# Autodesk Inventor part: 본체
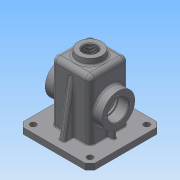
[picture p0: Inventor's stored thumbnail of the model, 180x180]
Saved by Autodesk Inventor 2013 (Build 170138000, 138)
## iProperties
Created: 2018-10
Part Number: 본체
Material: 일반
Document SubType Name: Modeling
Designer: Administrator
Density: 1 g/cm^3
Author: Administrator
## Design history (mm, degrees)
sketch "스케치1"
  geometry: L1 (-32.5, 32.5)-(32.5, 32.5); L2 (32.5, 32.5)-(32.5, -32.5); L3 (32.5, -32.5)-(-32.5, -32.5); L4 (-32.5, -32.5)-(-32.5, 32.5); L5 (-32.5, 32.5)-(32.5, -32.5); L6 (32.5, 32.5)-(-32.5, -32.5); 1 further point
  constraints: 12 end point, 2 midpoint, 2 parallel, 1 horizontal, 1 perpendicular
  dimensions: "d0" = 65 distance of L2.end L3.end; "d1" = 65 distance of L1.end L2.end
extrude "돌출1" new body sketch "스케치1" stored distance "d2" = 110; taper "d3" = 0 deg
sketch "스케치2"
  geometry: L1 (-110, 0)-(-110, 65) reference; C1 r 27.5 at (-55, 32.5); 2 further points
  constraints: 1 centre point, 1 horizontal alignment, 1 midpoint
  dimensions: "d4" = 55 diameter of C1; "d5" = 55 distance of point (-110, 32.5) C1.centre
feature "쉘1" dims "d6" = 5
fillet "모깎기1" dims "d7" = 8
fillet "모깎기2" dims "d8" = 8
extrude "돌출2" join sketch "스케치2" distance "d9" = 15; taper "d10" = 0 deg
sketch "스케치3"
  geometry: C1 r 27.5 at (0, 0) reference; C2 r 17.5 at (0, 0)
  constraints: 1 centre point, 1 coincident
  dimensions: "d11" = 35 diameter of C2
extrude "돌출3" cut sketch "스케치3" distance "d13" = 17; taper "d14" = 0 deg
sketch "스케치5"
  geometry: C1 r 27.5 at (-55, 24.5); 1 further point
  constraints: 1 centre point, 1 coincident
  dimensions: "d16" = 55 diameter of C1
extrude "돌출4" join sketch "스케치5" distance "d17" = 15; taper "d18" = 0 deg
sketch "스케치6"
  geometry: C1 r 27.5 at (0, 0) reference; C2 r 17.5 at (0, 0)
  constraints: 1 centre point, 1 coincident
  dimensions: "d20" = 35 diameter of C2
extrude "돌출5" cut sketch "스케치6" distance "d21" = 17; taper "d22" = 0 deg
sketch "스케치7"
  geometry: C1 r 17.5 at (0, 0) reference; C2 r 15 at (0, 0)
  constraints: 1 centre point, 1 coincident
  dimensions: "d23" = 30 diameter of C2
extrude "돌출6" cut sketch "스케치7" stored distance "d24" = 17; taper "d25" = 0 deg
sketch "스케치8"
  geometry: L1 (-32.5, 24.5)-(-32.5, -24.5) reference; L2 (-24.5, -32.5)-(24.5, -32.5) reference; L3 (32.5, -24.5)-(32.5, 24.5) reference; L4 (24.5, 32.5)-(-24.5, 32.5) reference; L5 (-60, 60)-(60, 60); L6 (60, 60)-(60, -60); L7 (60, -60)-(-60, -60); L8 (-60, -60)-(-60, 60); L9 (-60, 60)-(60, -60); L10 (60, 60)-(-60, -60); A1 r 8 centre (-24.5, 24.5) between (-24.5, 32.5) and (-32.5, 24.5) reference; A2 r 8 centre (-24.5, -24.5) between (-32.5, -24.5) and (-24.5, -32.5) reference; A3 r 8 centre (24.5, -24.5) between (24.5, -32.5) and (32.5, -24.5) reference; A4 r 8 centre (24.5, 24.5) between (32.5, 24.5) and (24.5, 32.5) reference; 1 further point
  constraints: 12 end point, 2 midpoint, 2 parallel, 1 horizontal, 1 perpendicular
  dimensions: "d26" = 120 distance of L5.start L5.end; "d28" = 120 distance of L5.end L6.end
extrude "돌출7" join sketch "스케치8" distance "d29" = 10; taper "d30" = 0 deg
chamfer "모따기1" distance "d31" = 8; stored, may be unused: second distance "d32" = 2, angle "d33" = 45 deg
node "작업 평면1"
sketch "스케치9"
  geometry: C1 r 20 at (0, 0); 1 further point
  constraints: 1 centre point, 1 coincident
  dimensions: "d35" = 40 diameter of C1
extrude "돌출8" join sketch "스케치9" stored distance "d36" = 10; taper "d37" = 7 deg
hole "구멍1" diameter "d40" = 22.835; stored, may be unused: countersink angle "d44" = 90 deg, drill point angle "d46" = 0 deg; dims "d41" = 20, "d42" = 4, "d43" = 2, "d45" = 20, "d116" = 10, "d117" = 10
sketch "스케치10"
  geometry: L1 (48, -45)-(40.815, -4.251); L2 (60, -45)-(60, -55) reference; L3 (52, -45)-(60, -45) reference; 1 further point
  constraints: 2 end point, 1 point on line
  dimensions: "d50" = 12 distance from line of L2 L1.start; "d52" = 10 deg angle of L2 L1
feature "리브1" sketch "스케치10" dims "d53" = 1, "d54" = 10, "d55" = 0, "d56" = 0, "d57" = 1, "d58" = 1
sketch "스케치11"
  geometry: L1 (-42.5, -29.454)-(-42.5, -45); L2 (52, -45)-(-52, -45) reference; L3 (-32.5, -45)-(-32.5, -12.49) reference; L4 (-27.5, 50)-(-27.5, -55) reference; 2 further points
  constraints: 2 end point, 1 point on line, 1 vertical
  dimensions: "d60" = 15 distance between parallel lines of L4 L1
fillet "모깎기5" dims "d61" = 3
fillet "모깎기6" dims "d62" = 3
feature "리브2" dims "d63" = 1, "d64" = 6, "d65" = 0, "d66" = 0, "d67" = 1, "d68" = 1
fillet "모깎기8" dims "d70" = 3
fillet "모깎기9" dims "d71" = 3
chamfer "모따기2" distance "d73" = 1; stored, may be unused: second distance "d74" = 2, angle "d75" = 45 deg
sketch "스케치12"
  geometry: L1 (0, 0)-(-21, 0); C1 r 18.5 at (0, 0) reference; 1 further point
  constraints: 2 end point, 1 coincident, 1 horizontal
  dimensions: "d77" = 21 distance of L1.start L1.end
hole "구멍2" sketch "스케치12" at (-21, 0) diameter "d78" = 3.242; stored, may be unused: countersink angle "d82" = 90 deg, drill point angle "d84" = 118 deg; dims "d79" = 8, "d80" = 4, "d81" = 2, "d83" = 10
fillet "모깎기11" dims "d88" = 3
chamfer "모따기3" distance "d89" = 1; stored, may be unused: second distance "d90" = 2, angle "d91" = 45 deg
fillet "모깎기15" dims "d95" = 3
fillet "모깎기17" dims "d97" = 3
sketch "스케치13"
  geometry: C1 r 5 at (-47.5, 47.5); C2 r 5 at (-47.5, -47.5); C3 r 5 at (47.5, 47.5); C4 r 5 at (47.5, -47.5); 1 further point
  constraints: 4 centre point, 2 horizontal alignment, 2 vertical alignment
  dimensions: "d99" = 10 diameter of C1; "d100" = 10 diameter of C2; "d101" = 10 diameter of C3; "d102" = 10 diameter of C4; "d103" = 95 distance of C4.centre C3.centre; "d104" = 95 distance of C3.centre C1.centre; "d105" = 47.5 horizontal distance of point (0, 0) C3.centre; "d106" = 47.5 horizontal distance of point (0, 0) C1.centre
extrude "돌출9" cut sketch "스케치13" distance "d107" = 10; taper "d108" = 0 deg
sketch "스케치14"
  geometry: L1 (0, 57)-(-92, 57) reference; L2 (18, 44.5)-(18, 4.5) reference; 1 further point
  constraints: 1 other
  dimensions: "d109" = 32.5 distance from line of point (-8, 24.5) L1; "d110" = 26 distance from line of L2 point (-8, 24.5)
feature "엠보싱1" sketch "스케치14" dims "d111" = 0.5, "d112" = 0
fillet "모깎기19" dims "d113" = 1
fillet "모깎기20" dims "d114" = 3
fillet "모깎기21" dims "d115" = 3
node "솔리드1"
mirror "대칭1"
mirror "대칭2"
pattern_circular "원형 패턴1" dims angle "d86" = 360 deg
mirror "대칭3"
other parameters: "d34" = 65
